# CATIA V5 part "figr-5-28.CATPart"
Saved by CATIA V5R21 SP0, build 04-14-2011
Part number: Part1
Bounding box of the stored display mesh (mm): x -100 to 100, y -100 to 100, z 0 to 57
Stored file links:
  D:\CATIA V5R21 E-RESOURCES\CATIA-V5R21\catia-v5r21-prt\c05-catia-v5r20-prt\catia-v5r21-figr-5-28.CATPart
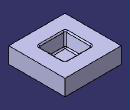
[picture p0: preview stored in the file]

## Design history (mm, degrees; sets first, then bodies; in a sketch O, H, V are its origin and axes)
Body1 (main body)
  Sketch1 on xy-plane, origin (0, 0, 0), H (1, 0, 0), V (0, 1, 0)
    line L1 (-100, 100) -> (100, 100)
    line L2 (100, 100) -> (100, -100)
    line L3 (100, -100) -> (-100, -100)
    line L4 (-100, -100) -> (-100, 100)
    axis line L5 (100, -100) -> (-100, 100)
    length L3 = 200
    length L2 = 200
    horizontal: L1 H, L3 H
    vertical: L2 V, L4 V
    midpoint: L5 O
  Pad1: profile Sketch1, direction (0, 0, 1), length 57
  Sketch2 on face of Pad1, origin (0, 0, 57), H (1, 0, 0), V (0, 1, 0)
    line L1 (-48.5141, 47.7936) -> (48.5141, 47.7936)
    line L2 (48.5141, 47.7936) -> (48.5141, -47.7936)
    line L3 (48.5141, -47.7936) -> (-48.5141, -47.7936)
    line L4 (-48.5141, -47.7936) -> (-48.5141, 47.7936)
    axis line L5 (48.5141, -47.7936) -> (-48.5141, 47.7936)
    horizontal: L1 H, L3 H
    vertical: L2 V, L4 V
    midpoint: O L5
  Pocket1: profile Sketch2, direction (0, 0, -1), length 42, opposite side up to face of Pad1
  Draft1: Angle 15, Neutral face of Pad1, PullDir face of Pocket1, SupportToDraft (face of Pocket1; face of Pocket1; face of Pocket1; face of Pocket1)
  Fillet1: radius 5, on edge [face of Pocket1 | face of Pocket1] (x4)
  Fillet2: radius 5, on edge [face of Pocket1 | face of Pocket1] (x4)
  Fillet3: radius 5, on edge [face of Pocket1 | face of Pad1]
